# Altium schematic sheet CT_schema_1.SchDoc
size 820 x 556 mm
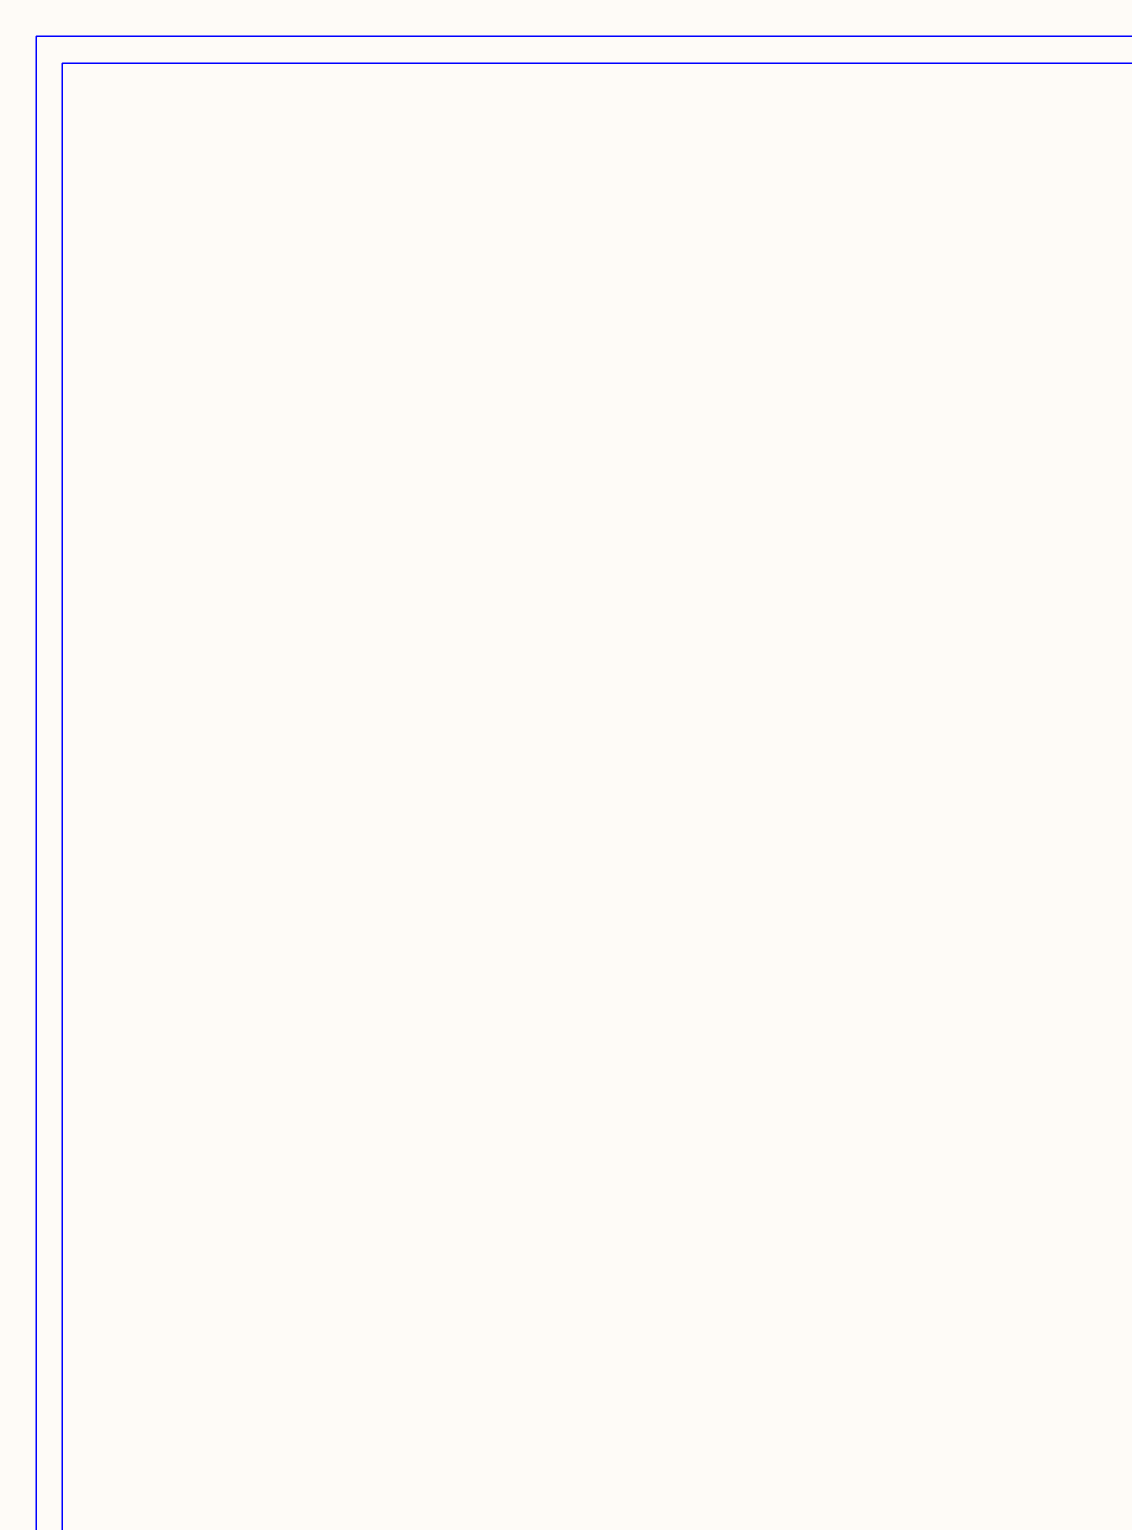
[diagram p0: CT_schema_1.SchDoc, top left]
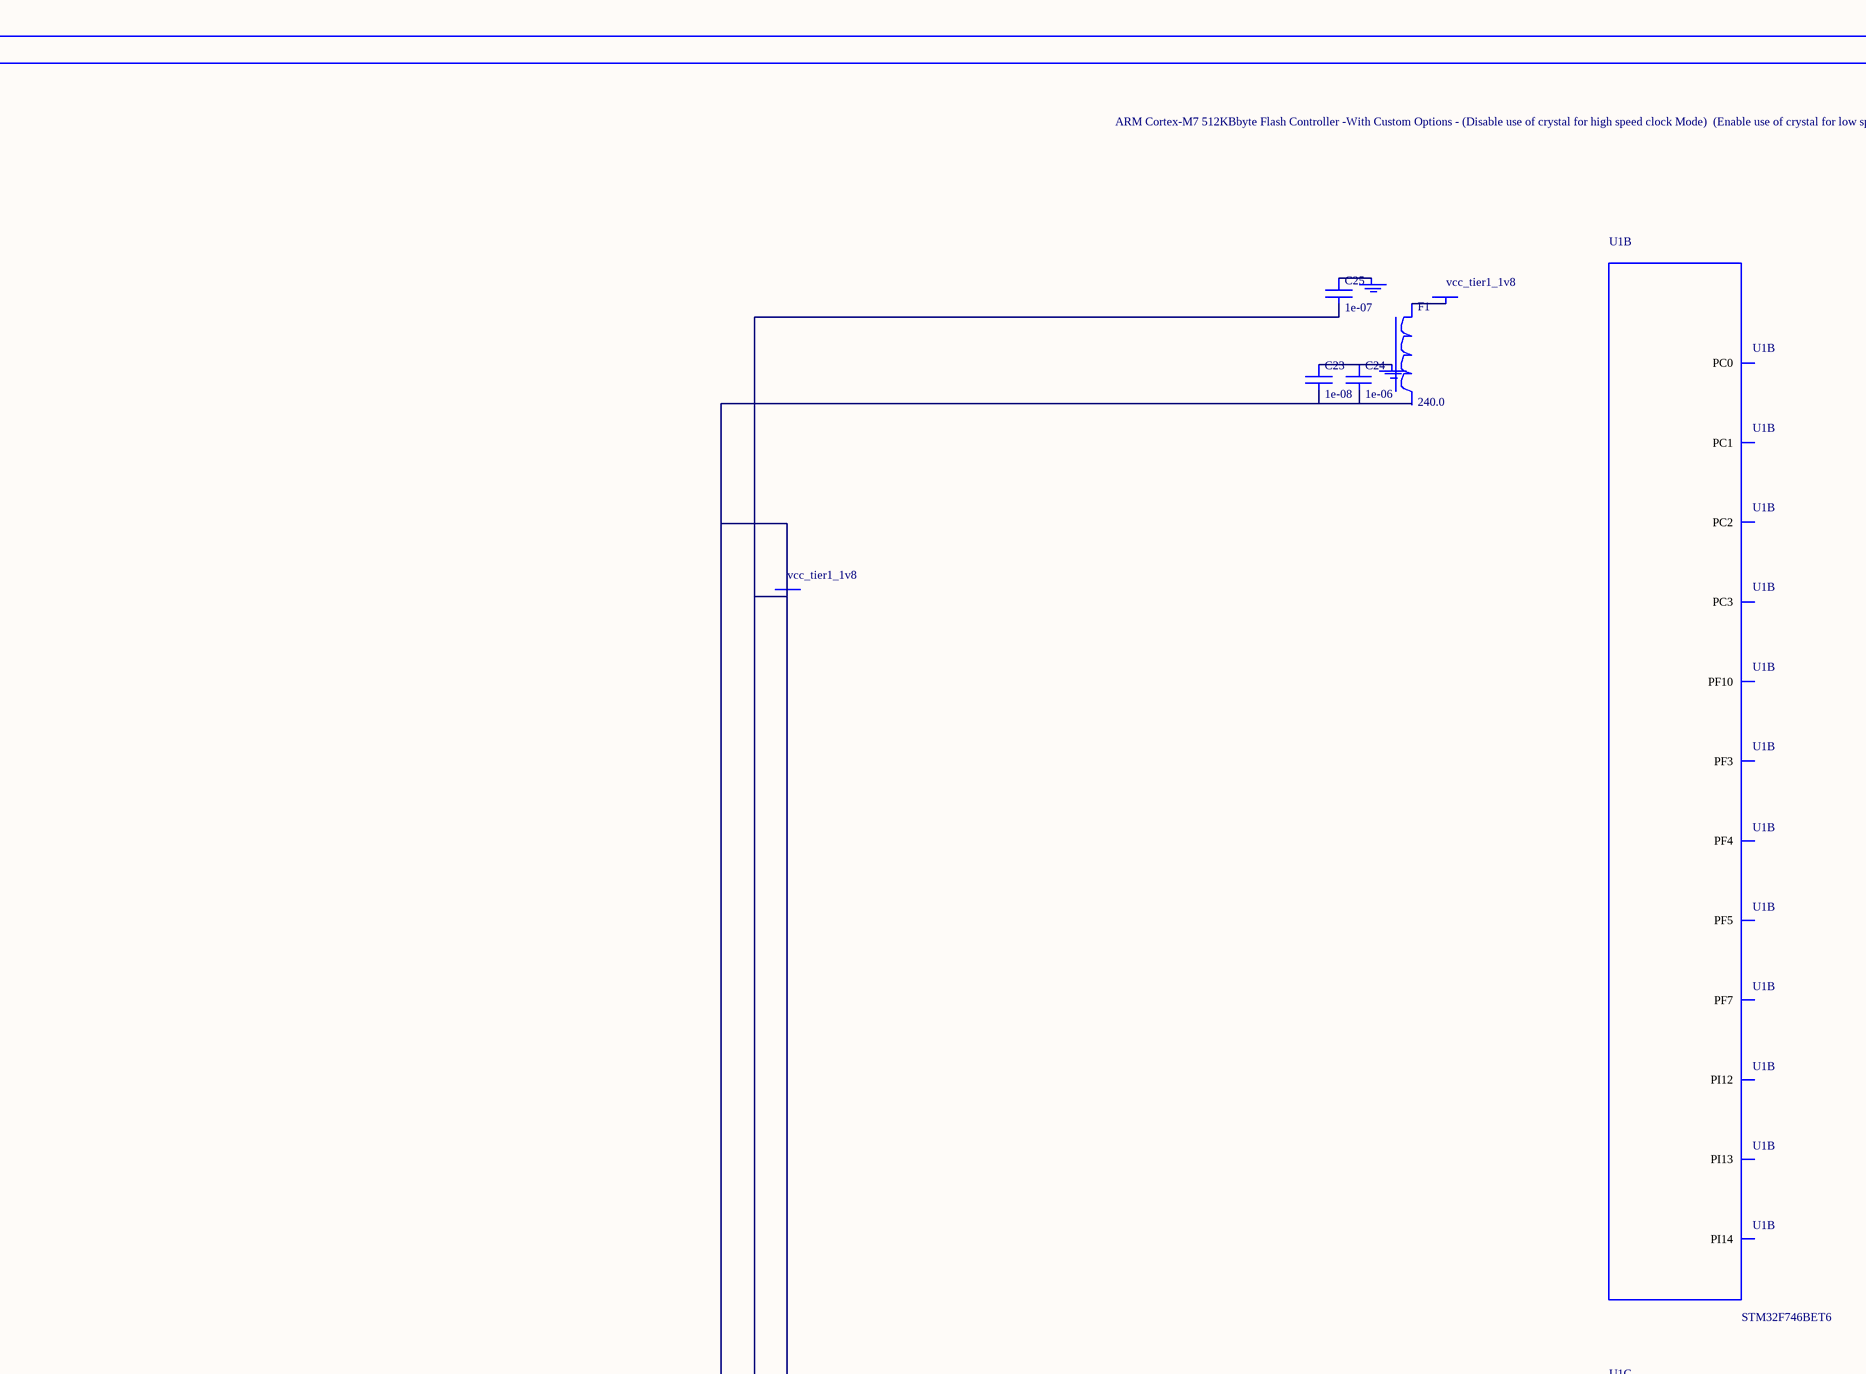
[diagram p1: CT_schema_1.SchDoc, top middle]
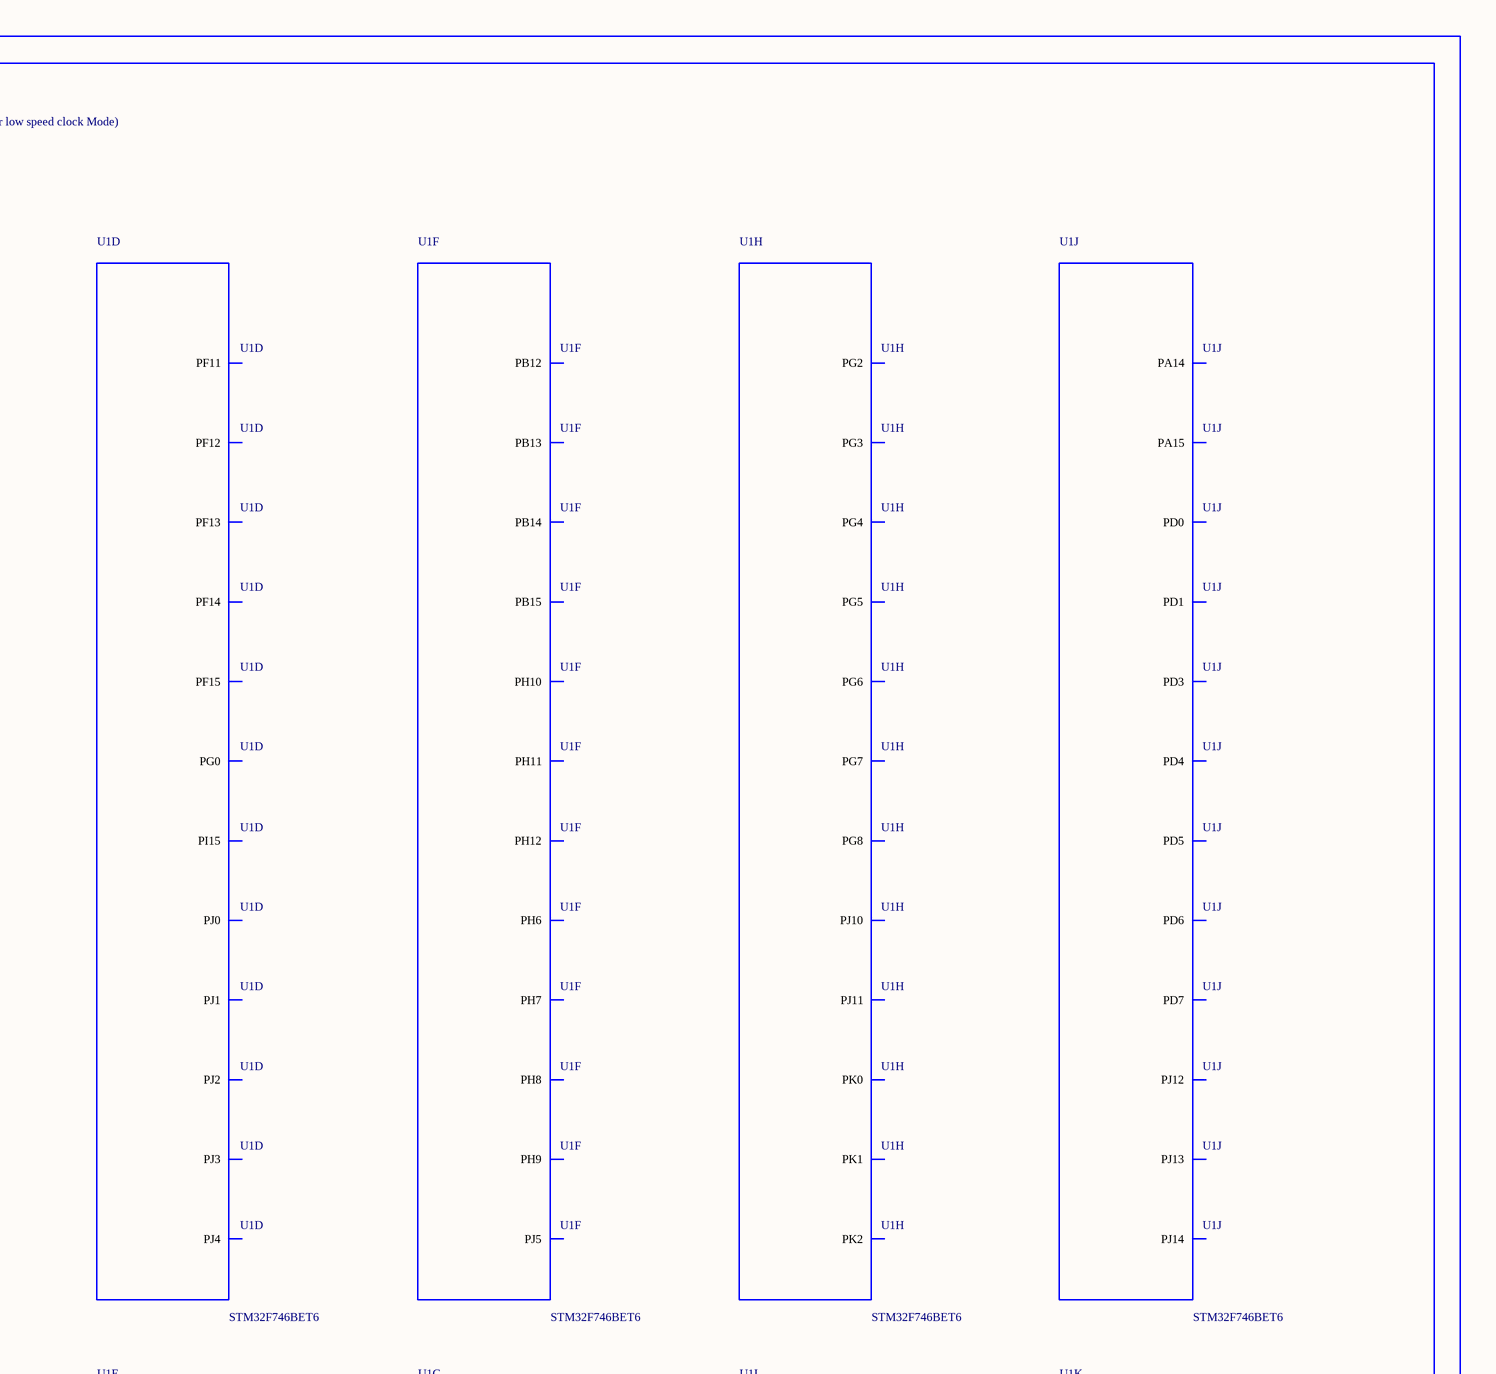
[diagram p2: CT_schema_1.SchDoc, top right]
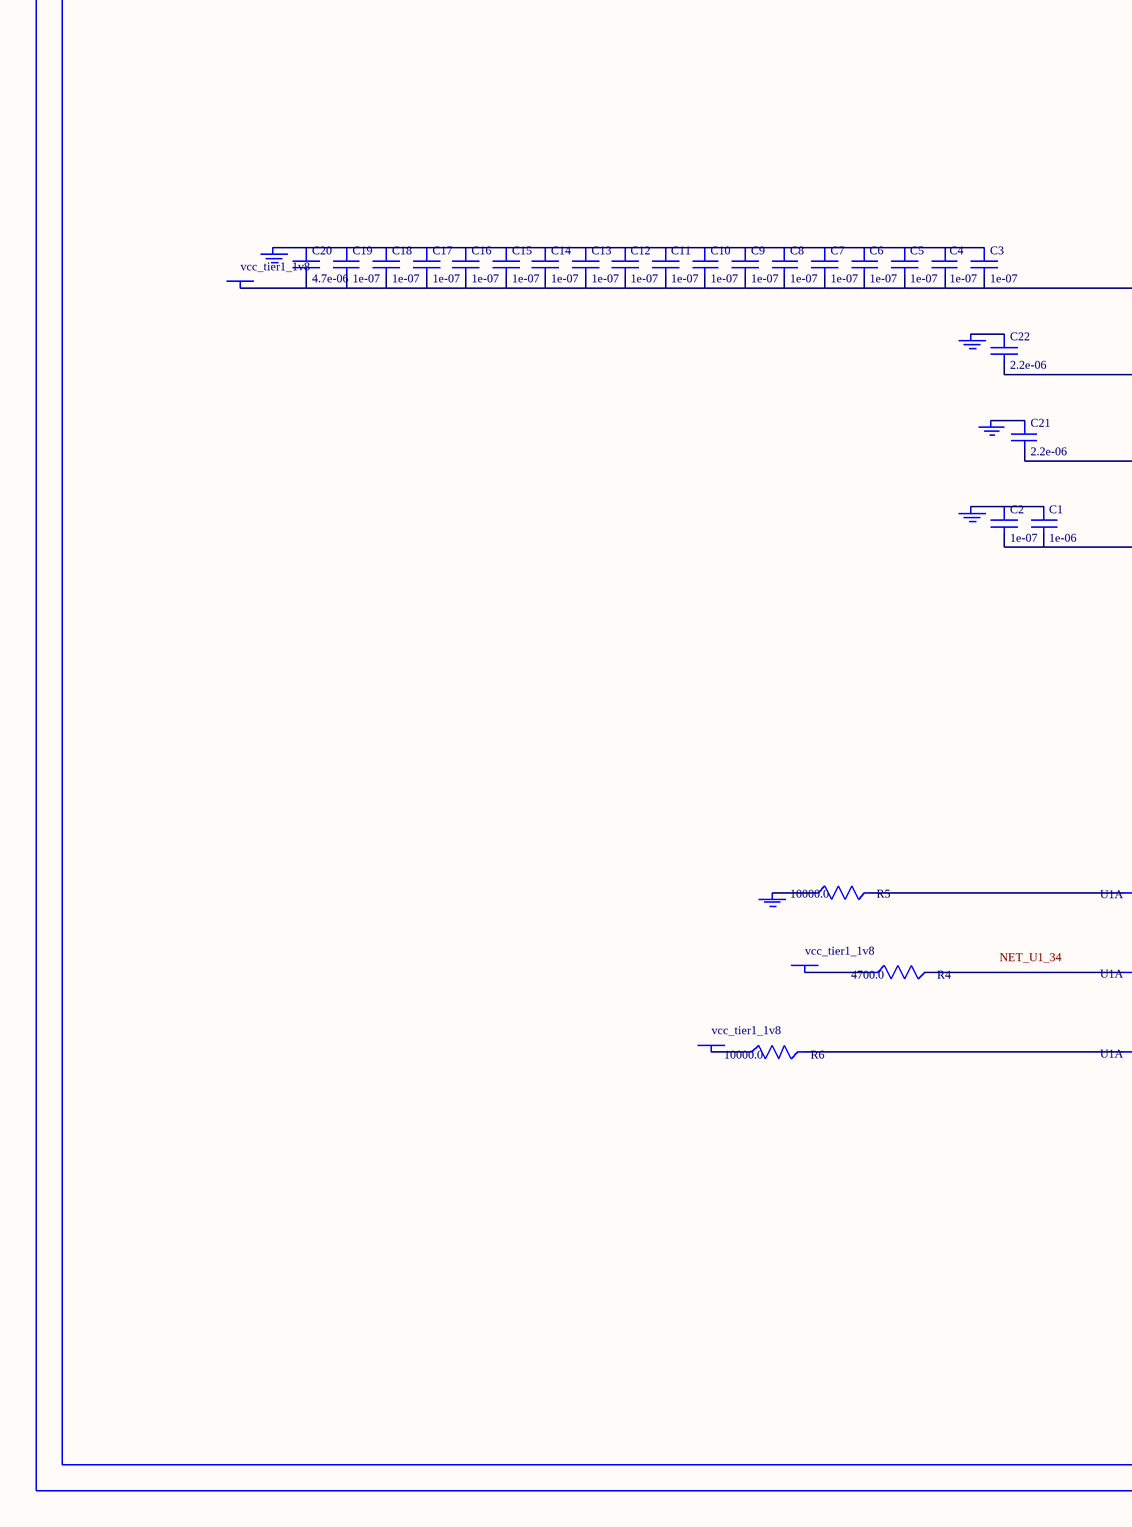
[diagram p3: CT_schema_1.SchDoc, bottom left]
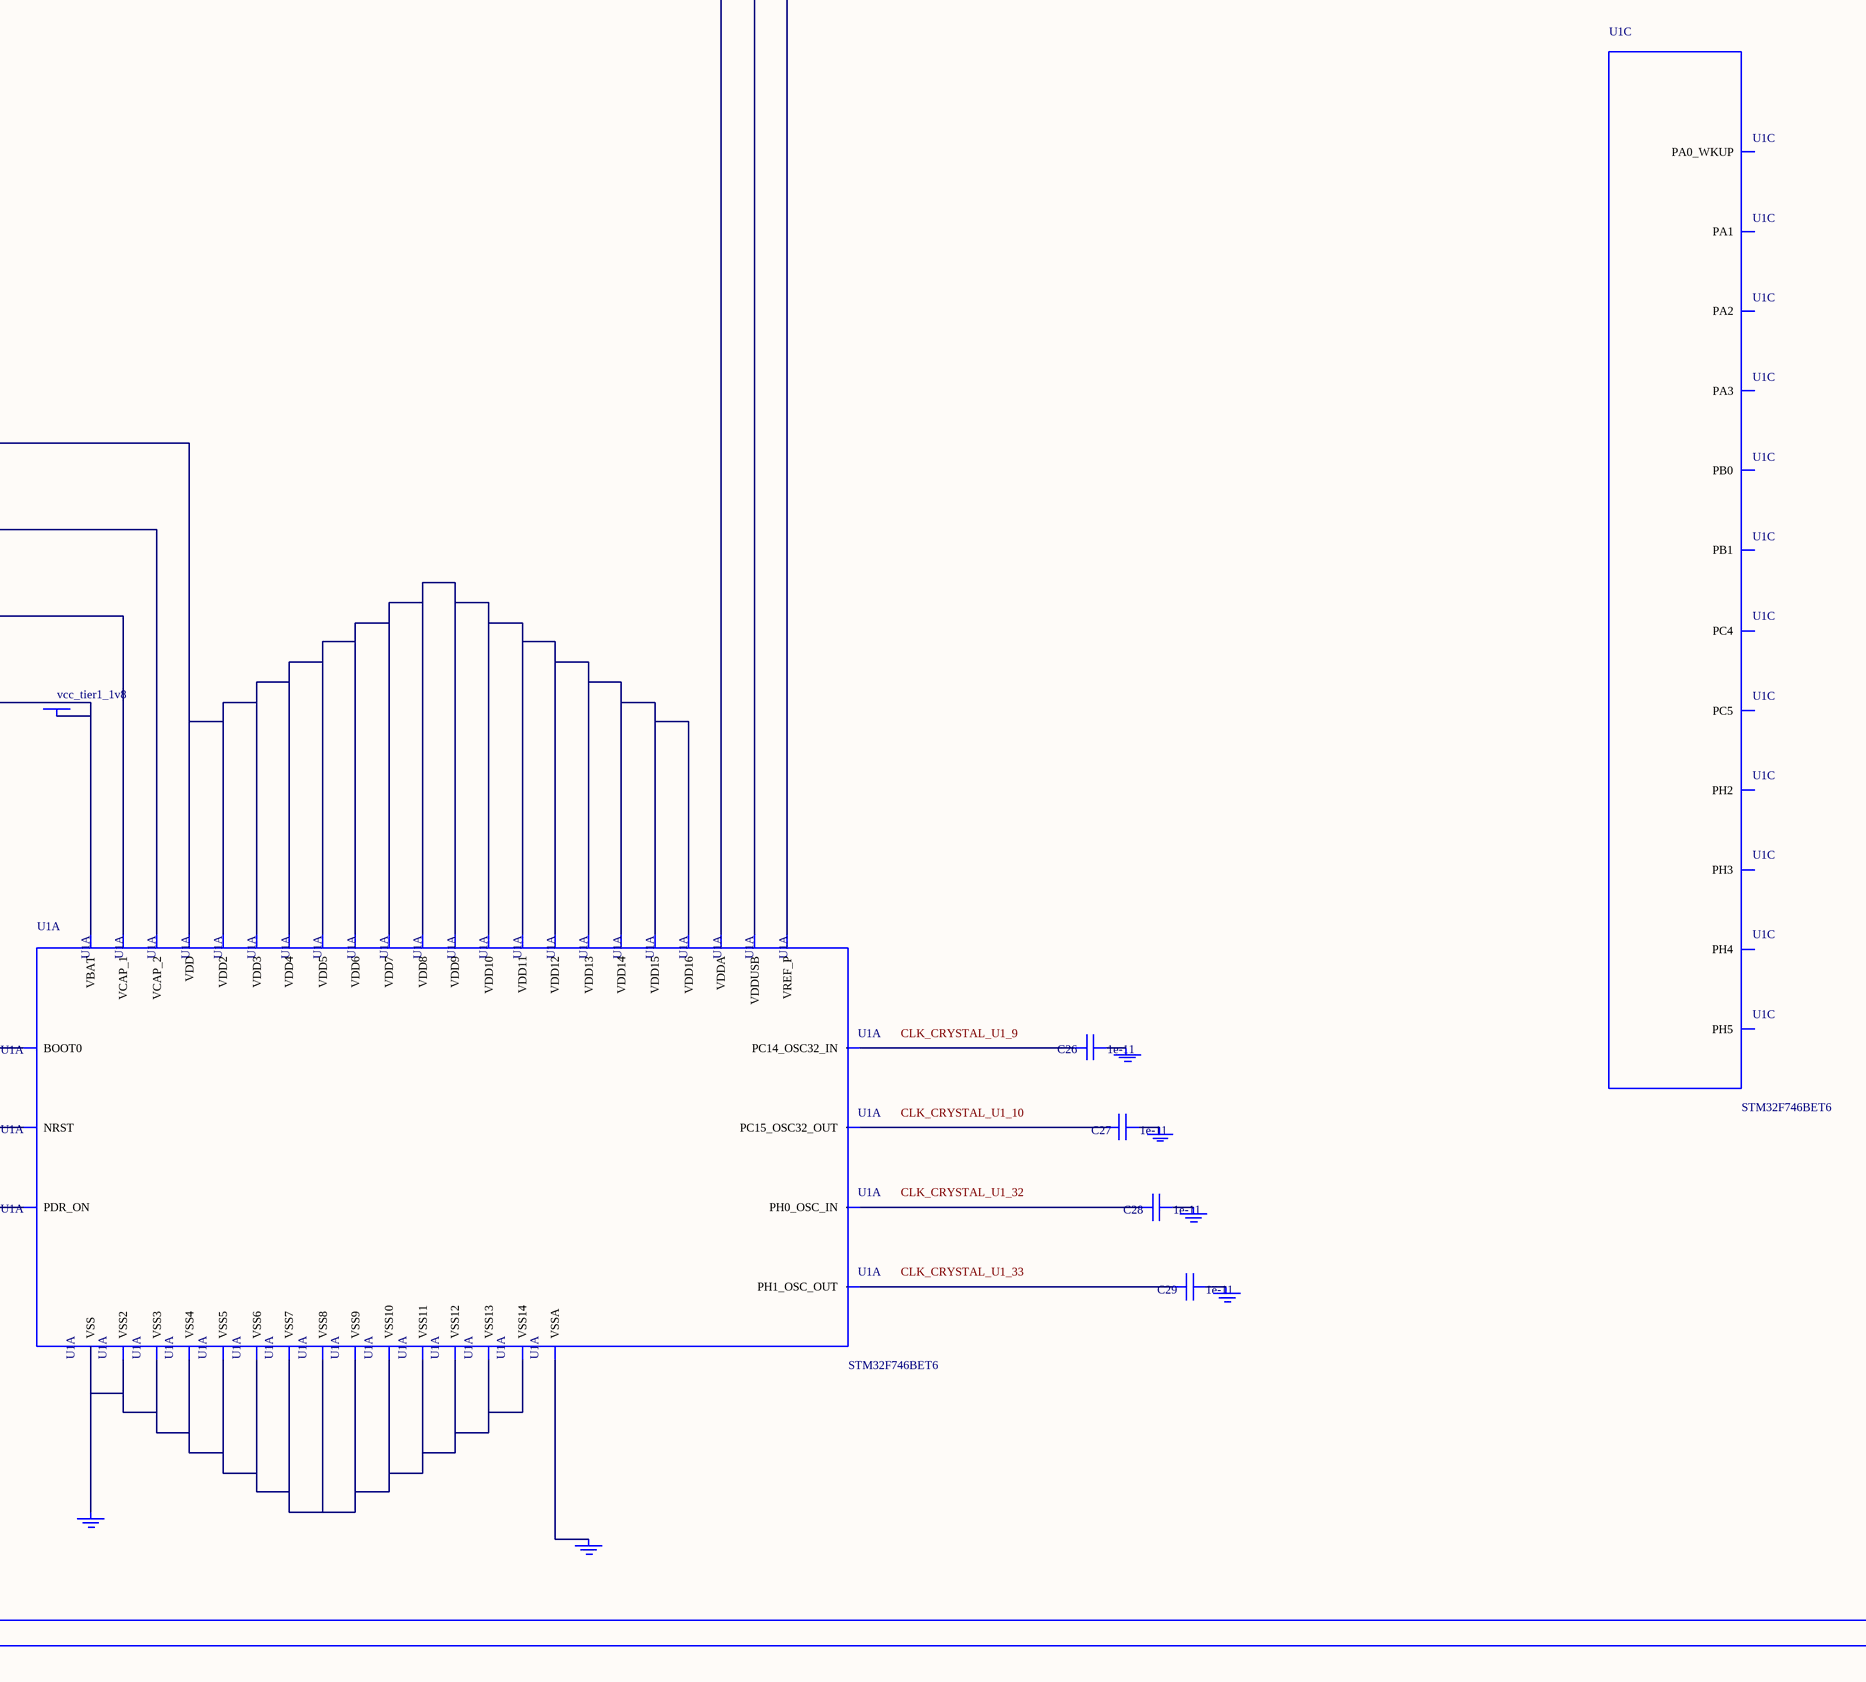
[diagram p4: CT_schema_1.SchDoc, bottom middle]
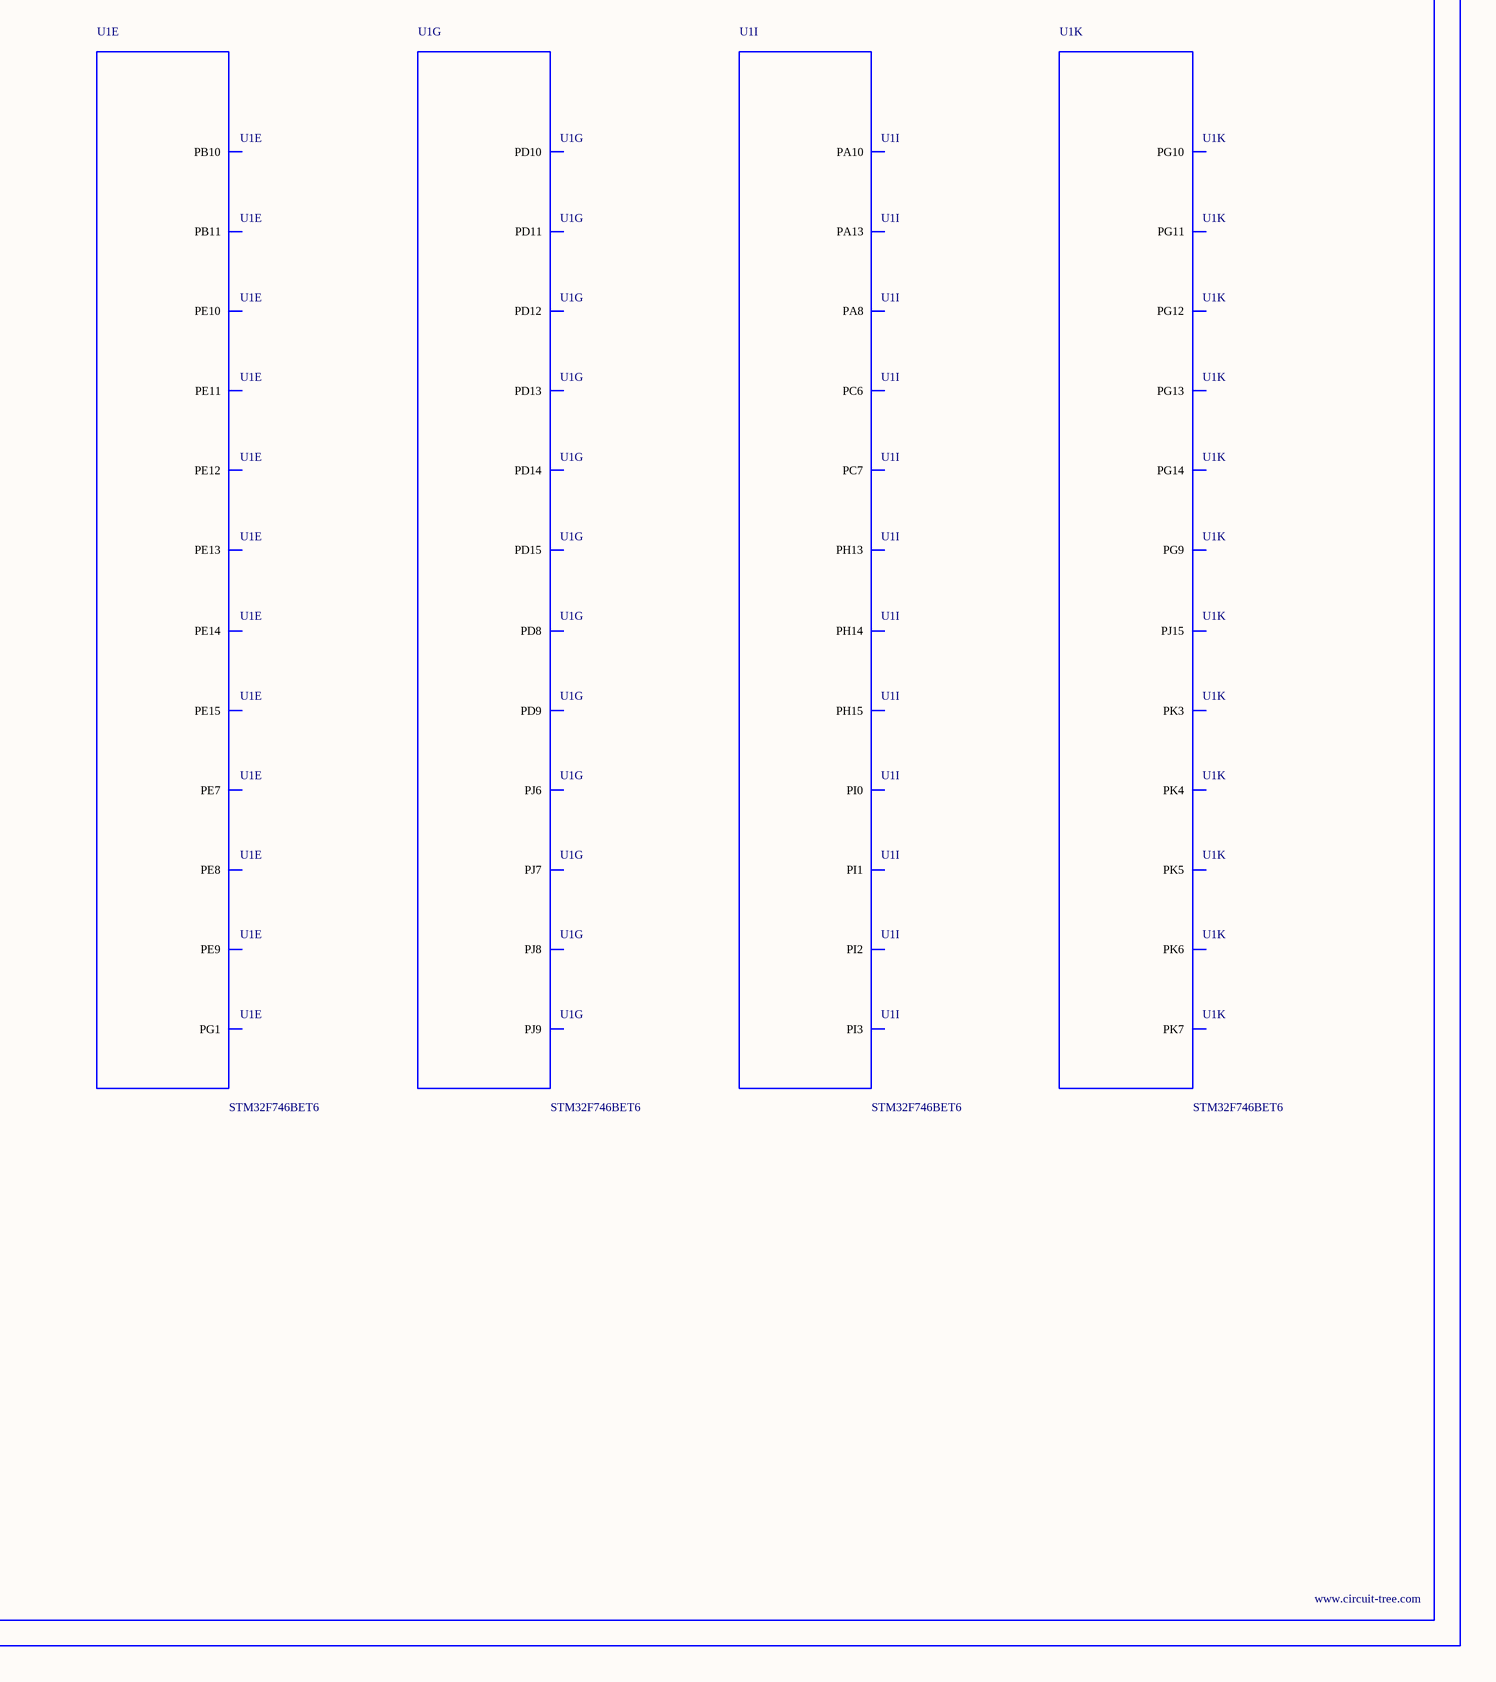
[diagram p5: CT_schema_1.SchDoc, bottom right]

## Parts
BORDER0  (no value)
C1  1e-06  [C0603]
C2  1e-07  [C0603]
C3  1e-07  [C0603]
C4  1e-07  [C0603]
C5  1e-07  [C0603]
C6  1e-07  [C0603]
C7  1e-07  [C0603]
C8  1e-07  [C0603]
C9  1e-07  [C0603]
C10  1e-07  [C0603]
C11  1e-07  [C0603]
C12  1e-07  [C0603]
C13  1e-07  [C0603]
C14  1e-07  [C0603]
C15  1e-07  [C0603]
C16  1e-07  [C0603]
C17  1e-07  [C0603]
C18  1e-07  [C0603]
C19  1e-07  [C0603]
C20  4.7e-06  [C0603]
C21  2.2e-06  [C0603]
C22  2.2e-06  [C0603]
C23  1e-08  [C0603]
C24  1e-06  [C0603]
C25  1e-07  [C0603]
C26  1e-11  [C0402]
C27  1e-11  [C0402]
C28  1e-11  [C0402]
C29  1e-11  [C0402]
F1  240.0  [L0603]
GND_INSTANCE_0_0  (no value)
GND_INSTANCE_0_1  (no value)
GND_INSTANCE_0_2  (no value)
GND_INSTANCE_0_3  (no value)
GND_INSTANCE_0_4  (no value)
GND_INSTANCE_0_5  (no value)
GND_INSTANCE_0_6  (no value)
GND_INSTANCE_0_7  (no value)
GND_INSTANCE_0_8  (no value)
GND_INSTANCE_0_9  (no value)
GND_INSTANCE_0_10  (no value)
GND_INSTANCE_0_11  (no value)
GND_INSTANCE_0_12  (no value)
POWER_INSTANCE_0_0  vcc_tier1_1v8
POWER_INSTANCE_0_1  vcc_tier1_1v8
POWER_INSTANCE_0_2  vcc_tier1_1v8
POWER_INSTANCE_0_3  vcc_tier1_1v8
POWER_INSTANCE_0_4  vcc_tier1_1v8
POWER_INSTANCE_0_5  vcc_tier1_1v8
R4  4700.0  [R0603]
R5  10000.0  [R0603]
R6  10000.0  [R0603]
U1  STM32F746BET6  [LQFP208]  (parts A,B,C,D,E,F,G,H,I,J,K of 15)

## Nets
NetC1_1: C1.1 C2.1 GND_INSTANCE_0_0.0(GND)
NetC1_2: C1.2 C2.2 POWER_INSTANCE_0_0.0(PWR) U1.6(VBAT)
NetC3_1: C3.1 C4.1 C5.1 C6.1 C7.1 C8.1 C9.1 C10.1 C11.1 C12.1 C13.1 C14.1 C15.1 C16.1 C17.1 C18.1 C19.1 C20.1 GND_INSTANCE_0_3.0(GND)
NetC3_2: C3.2 C4.2 C5.2 C6.2 C7.2 C8.2 C9.2 C10.2 C11.2 C12.2 C13.2 C14.2 C15.2 C16.2 C17.2 C18.2 C19.2 C20.2 POWER_INSTANCE_0_1.0(PWR) U1.15(VDD) U1.26(VDD2) U1.39(VDD3) U1.52(VDD4) U1.59(VDD5) U1.73(VDD6) U1.83(VDD7) U1.94(VDD8) U1.103(VDD9) U1.115(VDD10) U1.124(VDD11) U1.150(VDD12) U1.158(VDD13) U1.171(VDD14) U1.185(VDD15) U1.204(VDD16)
NetC21_1: C21.1 GND_INSTANCE_0_8.0(GND)
NetC21_2: C21.2 U1.92(VCAP_1)
NetC22_1: C22.1 GND_INSTANCE_0_10.0(GND)
NetC22_2: C22.2 U1.148(VCAP_2)
NetC23_1: C23.1 C24.1 GND_INSTANCE_0_7.0(GND)
NetC23_2: C23.2 C24.2 C25.2 POWER_INSTANCE_0_3.0(PWR) U1.41(VREF_P) U1.42(VDDA) U1.137(VDDUSB)
NetC25_1: C25.1 GND_INSTANCE_0_9.0(GND)
NetC26_1: C26.1 GND_INSTANCE_0_1.0(GND)
NetC26_2: C26.2 U1.9(PC14_OSC32_IN)
NetC27_1: C27.1 GND_INSTANCE_0_2.0(GND)
NetC27_2: C27.2 U1.10(PC15_OSC32_OUT)
NetC28_1: C28.1 GND_INSTANCE_0_4.0(GND)
NetC28_2: C28.2 U1.32(PH0_OSC_IN)
NetC29_1: C29.1 GND_INSTANCE_0_5.0(GND)
NetC29_2: C29.2 U1.33(PH1_OSC_OUT)
NetF1_1: F1.1 POWER_INSTANCE_0_2.0(PWR)
NetGND_INSTANCE_0_6_0: GND_INSTANCE_0_6.0(GND) U1.40(VSSA)
NetGND_INSTANCE_0_11_0: GND_INSTANCE_0_11.0(GND) R5.1
NetGND_INSTANCE_0_12_0: GND_INSTANCE_0_12.0(GND) U1.14(VSS) U1.25(VSS2) U1.51(VSS3) U1.60(VSS4) U1.72(VSS5) U1.82(VSS6) U1.93(VSS7) U1.114(VSS8) U1.125(VSS9) U1.136(VSS10) U1.149(VSS11) U1.170(VSS12) U1.184(VSS13) U1.202(VSS14)
NetPOWER_INSTANCE_0_4_0: POWER_INSTANCE_0_4.0(PWR) R6.1
NetPOWER_INSTANCE_0_5_0: POWER_INSTANCE_0_5.0(PWR) R4.1
NetR4_2: R4.2 U1.34(NRST)
NetR5_2: R5.2 U1.197(BOOT0)
NetR6_2: R6.2 U1.203(PDR_ON)

Not connected (* = marked no-connect by the designer): F1 2; U1 19(PI12) 20(PI13) 21(PI14) 22(PF3) 23(PF4) 24(PF5) 28(PF7) 31(PF10) 35(PC0) 36(PC1) 37(PC2) 38(PC3) 43(PA0_WKUP) 44(PA1) 45(PA2) 46(PH2) 47(PH3) 48(PH4) 49(PH5) 50(PA3) 57(PC4) 58(PC5) 61(PB0) 62(PB1) 64(PI15) 65(PJ0) 66(PJ1) 67(PJ2) 68(PJ3) 69(PJ4) 70(PF11) 71(PF12) 74(PF13) 75(PF14) 76(PF15) 77(PG0) 78(PG1) 79(PE7) 80(PE8) 81(PE9) 84(PE10) 85(PE11) 86(PE12) 87(PE13) 88(PE14) 89(PE15) 90(PB10) 91(PB11) 95(PJ5) 96(PH6) 97(PH7) 98(PH8) 99(PH9) 100(PH10) 101(PH11) 102(PH12) 104(PB12) 105(PB13) 106(PB14) 107(PB15) 108(PD8) 109(PD9) 110(PD10) 111(PD11) 112(PD12) 113(PD13) 116(PD14) 117(PD15) 118(PJ6) 119(PJ7) 120(PJ8) 121(PJ9) 122(PJ10) 123(PJ11) 126(PK0) 127(PK1) 128(PK2) 129(PG2) 130(PG3) 131(PG4) 132(PG5) 133(PG6) 134(PG7) 135(PG8) 138(PC6) 139(PC7) 142(PA8) 144(PA10) 147(PA13) 151(PH13) 152(PH14) 153(PH15) 154(PI0) 155(PI1) 156(PI2) 157(PI3) 159(PA14) 160(PA15) 164(PD0) 165(PD1) 167(PD3) 168(PD4) 169(PD5) 172(PD6) 173(PD7) 174(PJ12) 175(PJ13) 176(PJ14) 177(PJ15) 178(PG9) 179(PG10) 180(PG11) 181(PG12) 182(PG13) 183(PG14) 186(PK3) 187(PK4) 188(PK5) 189(PK6) 190(PK7)

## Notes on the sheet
- Labels drawn without touching a wire or pin: CLK_CRYSTAL_U1_9, CLK_CRYSTAL_U1_10, CLK_CRYSTAL_U1_32, CLK_CRYSTAL_U1_33, NET_U1_34

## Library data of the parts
BORDER0 = BORDER_PAGE0
C1 C24 = C0603C105K3RACTU
C2-C19 C25 = 06035C104K4Z2A
C20 = GRM188R6YA475KE15D
C21 C22 = C0603C225K8RACTU
C23 = 06035C103K4Z2A
C26-C29 = C0402C100K3GACTU
F1 = Z0603C241ASMST
GND_INSTANCE_0_0-GND_INSTANCE_0_12 = GND
POWER_INSTANCE_0_0-POWER_INSTANCE_0_5 = PWR
R4 = RC0603JR-074K7L
R5 R6 = RC0603JR-0710KL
